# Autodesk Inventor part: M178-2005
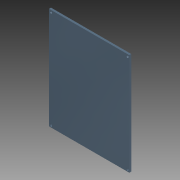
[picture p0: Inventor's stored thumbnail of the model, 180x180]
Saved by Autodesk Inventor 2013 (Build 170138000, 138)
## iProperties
Created: 2004-11
Part Number: M178-2005
Document SubType Name: Modeling
Designer: Autodesk, Inc.
Manufacturer: Standard
Standards Organization: Custom
Description: CABINET, PC, BASE PANEL
Mass: 1728.74 g
Surface Area: 3801.39 cm^2
Volume: 1728.74 cm^3
Density: 1 g/cm^3
Material: Allgemein
CAGE: 1LJX3
Dept. ID: Product Design
Description #2: ---
Finish #1: ---
Finish #2: ---
Material ID: ---
Project Number: ---
Author: Autodesk, Inc.
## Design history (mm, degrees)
sketch "Sketch1"
  geometry: L1 (-189.23, 240.03)-(189.23, 240.03); L2 (189.23, 240.03)-(189.23, -240.03); L3 (189.23, -240.03)-(-189.23, -240.03); L4 (-189.23, -240.03)-(-189.23, 240.03); 3 further points
  constraints: 8 end point, 2 midpoint, 2 parallel, 1 horizontal, 1 horizontal alignment, 1 perpendicular, 1 vertical alignment
  dimensions: "d0" = 378.46 distance of L1.start L1.end; "d1" = 480.06 distance of L3.end L1.start
extrude "Extrusion1" new body sketch "Sketch1" distance "d2" = 9.525; taper "d3" = 0 deg
sketch "Sketch2"
  geometry: L1 (189.23, -240.03)-(-189.23, -240.03) reference; L2 (189.23, 240.03)-(189.23, -240.03) reference; 1 further point
  dimensions: "d4" = 8.73 distance from line of L1 point (180.5, -231.3); "d5" = 8.73 distance from line of point (180.5, -231.3) L2
hole "Hole1" sketch "Sketch2" diameter "d6" = 6.604; stored, may be unused: countersink angle "d10" = 90 deg, drill point angle "d12" = 118 deg; dims "d7" = 12.7, "d8" = 12.5984, "d9" = 6.35, "d11" = 19.05
mirror "Mirror1"
mirror "Mirror2"
body "Solid1"
